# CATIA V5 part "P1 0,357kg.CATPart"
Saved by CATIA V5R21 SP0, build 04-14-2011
Part number: Part1.1
Material "Aluminium": density 2710 kg/m3, Young's modulus 7e+10 Pa, Poisson ratio 0.346, thermal expansion 2.36e-05 1/K
Bounding box of the stored display mesh (mm): x 0 to 82, y -68 to 68, z 2.906 to 18.906
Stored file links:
  C:\Users\HP\Desktop\Mes Fichiers\CATIA V5\Mini Projet\Projet 1\P1 0,357kg.CATPart
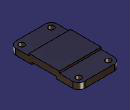
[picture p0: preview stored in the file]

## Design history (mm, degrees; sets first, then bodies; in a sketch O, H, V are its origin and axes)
AxisSystem1: origin (0, 0, 0), X (1, 0, 0), Y (0, 1, 0), Z (0, 0, 1)
Body1 (main body), material "Aluminium"
  Sketch1 on YZ plane of AxisSystem1, origin (0, 0, 0), H (0, 1, 0), V (0, 0, 1)
    line L1 (-24, 2.906) -> (-24, 6.906)
    line L2 (-24, 6.906) -> (24, 6.906)
    line L3 (24, 6.906) -> (24, 2.906)
    line L4 (24, 2.906) -> (68, 2.906)
    line L5 (68, 2.906) -> (68, 14.906)
    line L6 (68, 14.906) -> (30, 14.906)
    line L7 (30, 14.906) -> (30, 18.906)
    line L8 (30, 18.906) -> (-30, 18.906)
    line L9 (-30, 18.906) -> (-30, 14.906)
    point P10 (-30, 14.906)
    line L10 (-30, 14.906) -> (-68, 14.906)
    line L11 (-68, 14.906) -> (-68, 2.906)
    point P12 (-68, 2.906)
    line L12 (-68, 2.906) -> (-24, 2.906)
    reference projected line E1 through (0, 0) direction (0, 1) from edge [ZX plane of AxisSystem1 | YZ plane of AxisSystem1]
    length L2 = 48
    length L12 = 44
    distance L8 L6 = 4
    distance L6 L4 = 12
    distance L2 L4 = 4
    length L10 = 38
    length L6 = 38
    vertical: L1 V, L3 V, L5 V, L7 V, L9 V, L11 V
    horizontal: L2 H, L4 H, L6 H, L8 H, L10 H, L12 H
    coincidence: P10 L6, P12 L4
    symmetry: L5 L11 V, L1 L3 E1
  Pad1: profile Sketch1, direction (1, 0, 0), length 82
  Fillet1: radius 12, on edge [face of Pad1 from Sketch1.L5 | end face of Pad1]; edge [start face of Pad1 | face of Pad1 from Sketch1.L5]; edge [start face of Pad1 | face of Pad1 from Sketch1.L11]; edge [face of Pad1 from Sketch1.L11 | end face of Pad1]
  Sketch2 on face of Pad1 from Sketch1.L10, origin (0, 0, 14.906), H (1, 0, 0), V (0, 1, 0)
    point P1 (70, 56)
    reference projected arc E1 centre (70, 56) radius 12 from (82, 56) to (70, 68) ccw from edge [face of Pad1 from Sketch1.L6 | face of Fillet1]
    reference projected line E2 through (0, 0) direction (1, 0) from edge [XY plane of AxisSystem1 | ZX plane of AxisSystem1]
    point P4 (70, -56)
    point P5 (12, 56)
    reference projected arc E3 centre (12, 56) radius 12 from (12, 68) to (0, 56) ccw from edge [face of Pad1 from Sketch1.L6 | face of Fillet1]
    reference projected line E4 through (0, 0) direction (1, 0) from edge [XY plane of AxisSystem1 | ZX plane of AxisSystem1]
    point P8 (12, -56)
    concentricity: P1 E1, P5 E3
    symmetry: P1 P4 E2, P5 P8 E4
  Sketch3 on face of Pad1 from Sketch1.L10, origin (12, -56, 14.906), H (1, 0, 0), V (0, 1, 0)
    point P1 (0, 0)
    reference projected point E1 (0, 0) from Sketch2.P8
    coincidence: E1 P1
  Hole1: placed by Sketch3, at (12, -56, 14.906) direction (0, 0, -1), diameter 11, through (limit type 3)
  Sketch4 on face of Pad1 from Sketch1.L6, origin (70, 56, 14.906), H (1, 0, 0), V (0, 1, 0)
    point P1 (0, 0)
    reference projected point E1 (0, 0) from Sketch2.P1
    coincidence: E1 P1
  Hole2: placed by Sketch4, at (70, 56, 14.906) direction (0, 0, -1), diameter 11, through (limit type 3)
  Sketch5 on face of Pad1 from Sketch1.L6, origin (12, 56, 14.906), H (1, 0, 0), V (0, 1, 0)
    point P1 (0, 0)
    reference projected point E1 (0, 0) from Sketch2.P5
    coincidence: E1 P1
  Hole3: placed by Sketch5, at (12, 56, 14.906) direction (0, 0, -1), diameter 11, through (limit type 3)
  Sketch6 on face of Pad1 from Sketch1.L10, origin (70, -56, 14.906), H (1, 0, 0), V (0, 1, 0)
    point P1 (0, 0)
    reference projected point E1 (0, 0) from Sketch2.P4
    coincidence: E1 P1
  Hole4: placed by Sketch6, at (70, -56, 14.906) direction (0, 0, -1), diameter 11, through (limit type 3)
